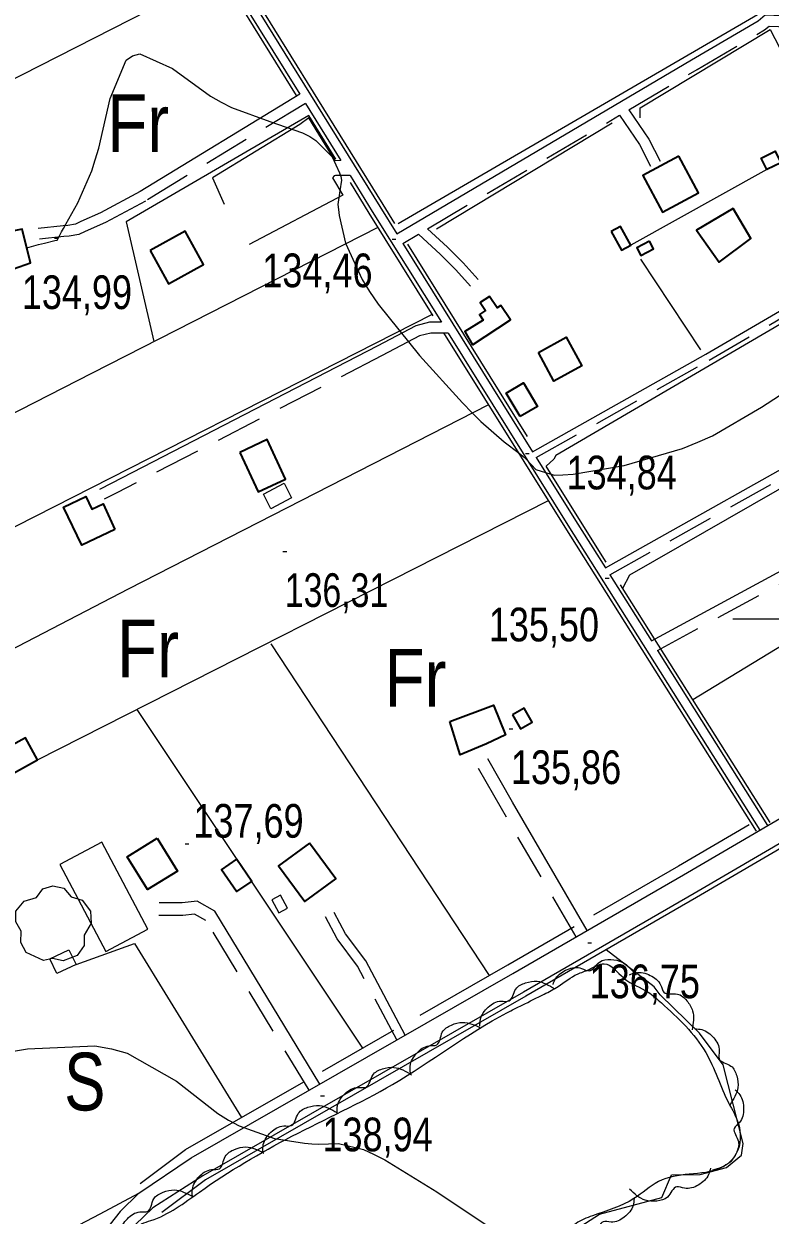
# Model space of a CAD drawing. Extents: x 487425 to 492029, y 4383576 to 4386788.
# Drawn here: x 490290.9 to 490484.7, y 4384845.1 to 4385154.5 of the extents above; entities that cross this region are included whole.
import ezdxf
from ezdxf.enums import TextEntityAlignment as Align

# ---------------------------------------------------------------- set-up
doc = ezdxf.new("R2010")
doc.units = 0
doc.header["$LTSCALE"] = 4
doc.linetypes.add('LONG_DASHED', pattern=[7.5, 6, -1.5])
doc.linetypes.add('MEDIUM_DASHED', pattern=[4.5, 3, -1.5])
for name, color, linetype, lineweight in [('1', 7, 'Continuous', 13), ('21', 7, 'Continuous', 25), ('25', 7, 'LONG_DASHED', 25), ('27', 7, 'Continuous', 25), ('29', 7, 'Continuous', 13), ('36', 7, 'Continuous', 25), ('38', 7, 'Continuous', 25), ('47', 7, 'Continuous', 35), ('51', 7, 'Continuous', 13), ('58', 7, 'Continuous', 25), ('7', 7, 'Continuous', 13), ('9', 7, 'Continuous', 13)]:
    doc.layers.add(name, color=color, linetype=linetype, lineweight=lineweight)
doc.layers.add('31', color=7, linetype='Continuous')

msp = doc.modelspace()

# ---------------------------------------------------------------- linework, layer by layer
at = {"layer": '1'}
msp.add_line((490475, 4385000), (490525, 4385000), dxfattribs=at)
at = {"layer": '21'}
for points in [[(490353.07, 4385032.38), (490358.44, 4385035.18), (490360.42, 4385031.38), (490355.05, 4385028.58)], [(490355.23, 4384927.03), (490357.08, 4384923.61), (490359.35, 4384924.84), (490357.5, 4384928.26)], [(490297.6, 4384911.68), (490302.57, 4384914.07), (490304.42, 4384910.24), (490299.45, 4384907.85)]]:
    msp.add_lwpolyline(points, close=True, dxfattribs=at)
at = {"layer": '25'}
msp.add_lwpolyline([(490433.1, 4384840.72), (490440.38, 4384845.42), (490456.52, 4384849.72), (490459.08, 4384855.56), (490466.51, 4384855.68), (490473.34, 4384857.54), (490477.24, 4384860.68), (490477.7, 4384863.75), (490472.44, 4384884.16), (490466.32, 4384892.43), (490456.15, 4384902.35), (490454.58, 4384904.46), (490442.06, 4384914.01)], dxfattribs=at)
at = {"layer": '27'}
for points in [[(490617.37, 4384698.42), (490601.81, 4384693.62), (490591.76, 4384693.65), (490581.71, 4384693.68), (490576.91, 4384694.3), (490571.22, 4384695.74), (490565.38, 4384696.95), (490561.4, 4384697.79), (490559.68, 4384698.32), (490552.49, 4384698.94), (490550.31, 4384698.35), (490522.61, 4384686.74), (490495.9, 4384680.59), (490488.46, 4384676.27), (490488.9, 4384674.24), (490493.38, 4384666.5), (490491.11, 4384661.41), (490488.03, 4384658.87), (490483.15, 4384656.04), (490478.87, 4384655.6), (490473.86, 4384657.12), (490454.42, 4384678.39), (490426.55, 4384709.07), (490413.85, 4384725.6), (490390.23, 4384749.37), (490372.38, 4384771.02), (490352.04, 4384791.1), (490332.69, 4384812.23), (490324.39, 4384821.02), (490321.78, 4384824.26), (490318.42, 4384829.14), (490316.41, 4384834.54), (490317.92, 4384838.06), (490319.65, 4384841.28), (490321.46, 4384842.85), (490323.86, 4384843.74), (490336.48, 4384851.13), (490360.44, 4384865.6), (490386.65, 4384879.1), (490416.32, 4384897.68), (490420.3, 4384899.69), (490426.01, 4384902.52), (490429.62, 4384904.53), (490434.65, 4384907.74), (490437.65, 4384908.93), (490441.55, 4384910.42), (490446.72, 4384906.66), (490453, 4384903.04), (490456.45, 4384900.25), (490467.95, 4384887.4), (490473.91, 4384874.26), (490476.44, 4384868.85), (490475.9, 4384861.13), (490472.06, 4384857.47), (490463.66, 4384855.77), (490455.7, 4384853.84), (490449.32, 4384849.44), (490438.51, 4384844.97), (490434.3, 4384842.96), (490429.94, 4384837.43), (490427.66, 4384828.43), (490427.25, 4384816.89), (490427.97, 4384807.51), (490429.3, 4384801.21), (490433.76, 4384787.33), (490439.88, 4384776.81), (490445.4, 4384769.75), (490455.04, 4384758.25), (490456.23, 4384753.97), (490456.81, 4384748.79), (490460.93, 4384747.06), (490467.91, 4384747.86), (490498.23, 4384759.32), (490526.16, 4384771.3), (490535.17, 4384775.92), (490539.68, 4384778.53), (490555.38, 4384788.38), (490560.34, 4384793.09), (490556.85, 4384802.33), (490547.98, 4384822.07), (490542.69, 4384831.84), (490537.93, 4384843.62), (490531.01, 4384861.41), (490527.97, 4384873.04), (490519.06, 4384879.07), (490516.75, 4384882.98), (490514.9, 4384889.28), (490519.37, 4384907.19), (490528.34, 4384921.18), (490538.42, 4384933.3), (490552.62, 4384941.58)], [(490428.3, 4384905), (490429.02, 4384906.63), (490432.03, 4384908.93), (490435.72, 4384909.22), (490437.67, 4384908.57), (490440.38, 4384910.87), (490443.3, 4384911.51), (490446.25, 4384910.85), (490449.86, 4384907.46)], [(490448.12, 4384907.53), (490449.8, 4384908.09), (490453.53, 4384907.41), (490456.24, 4384904.9), (490457.07, 4384903.02), (490460.59, 4384902.55), (490463.03, 4384900.83), (490464.54, 4384898.21), (490464.45, 4384893.25)], [(490409.32, 4384894.19), (490409.44, 4384895.96), (490411.49, 4384899.16), (490414.84, 4384900.71), (490416.89, 4384900.77), (490418.65, 4384903.85), (490421.17, 4384905.45), (490424.17, 4384905.86), (490428.73, 4384903.9)], [(490391.28, 4384882.06), (490391.21, 4384883.83), (490392.91, 4384887.22), (490396.08, 4384889.11), (490398.12, 4384889.38), (490399.55, 4384892.63), (490401.89, 4384894.49), (490404.83, 4384895.2), (490409.57, 4384893.73)], [(490465.15, 4384893.5), (490466.91, 4384893.32), (490470.04, 4384891.17), (490471.48, 4384887.77), (490471.46, 4384885.72), (490474.49, 4384883.85), (490476, 4384881.28), (490476.3, 4384878.27), (490474.19, 4384873.78)], [(490372.2, 4384871.76), (490372.31, 4384873.53), (490374.33, 4384876.74), (490377.67, 4384878.31), (490379.73, 4384878.38), (490381.47, 4384881.47), (490383.99, 4384883.09), (490386.98, 4384883.51), (490391.55, 4384881.58)], [(490475.59, 4384877.66), (490476.82, 4384876.38), (490477.8, 4384872.72), (490476.69, 4384869.2), (490475.35, 4384867.64), (490476.43, 4384864.26), (490475.91, 4384861.33), (490474.19, 4384858.84), (490469.67, 4384856.79)], [(490352.97, 4384861.7), (490353.06, 4384863.47), (490355.05, 4384866.7), (490358.37, 4384868.31), (490360.42, 4384868.4), (490362.14, 4384871.52), (490364.63, 4384873.16), (490367.62, 4384873.61), (490372.21, 4384871.74)], [(490334.65, 4384850.02), (490334.63, 4384851.8), (490336.41, 4384855.15), (490339.63, 4384856.96), (490341.67, 4384857.18), (490343.18, 4384860.4), (490345.56, 4384862.2), (490348.52, 4384862.84), (490353.22, 4384861.26)], [(490469.17, 4384857.36), (490468.69, 4384855.66), (490466.02, 4384852.95), (490462.43, 4384852.13), (490460.41, 4384852.5), (490458.04, 4384849.84), (490455.24, 4384848.8), (490452.23, 4384849.02), (490448.17, 4384851.88)], [(490315.89, 4384839.12), (490315.9, 4384840.89), (490317.75, 4384844.21), (490321, 4384845.96), (490323.04, 4384846.14), (490324.61, 4384849.33), (490327.03, 4384851.08), (490330, 4384851.67), (490334.67, 4384850)], [(490449.34, 4384849.42), (490449.09, 4384847.66), (490446.81, 4384844.63), (490443.36, 4384843.33), (490441.31, 4384843.43), (490439.32, 4384840.48), (490436.68, 4384839.07), (490433.67, 4384838.89), (490429.27, 4384841.18)]]:
    msp.add_spline(points, degree=3, dxfattribs=at)
at = {"layer": '29'}
msp.add_lwpolyline([(490296, 4384911.26), (490291.46, 4384913.38), (490290.05, 4384915.92), (490290.15, 4384918.9), (490288.78, 4384921.31), (490288.82, 4384924.06), (490290.98, 4384926.66), (490294.17, 4384927.66), (490295.82, 4384929.85), (490298.39, 4384930.68), (490301.25, 4384930.03), (490303.2, 4384927.76), (490306.01, 4384926.94), (490308.14, 4384924.09), (490308.38, 4384920.96), (490306.5, 4384917.81), (490306.5, 4384915.13), (490304.68, 4384912.52), (490301.06, 4384911.18), (490298.29, 4384911.81)], close=True, dxfattribs=at)
at = {"layer": '36'}
for points in [[(490810.5, 4385130.98), (490748.83, 4385094.26), (490648.55, 4385035.69), (490532.81, 4384968.32), (490464.98, 4384928.7), (490420.66, 4384903.02), (490337.39, 4384855.31), (490324.37, 4384847.05)], [(490320.75, 4384850.81), (490334.31, 4384860.01), (490417.86, 4384907.88), (490462.16, 4384933.55), (490529.98, 4384973.17), (490560.7, 4384991.06)], [(490320.75, 4384850.81), (490315.86, 4384846.11), (490311.96, 4384841.17), (490311.11, 4384835.98), (490311.09, 4384829.32), (490311.85, 4384823.86), (490315.09, 4384817.04), (490319.53, 4384811.61), (490326.04, 4384805.35)], [(490324.37, 4384847.05), (490319.74, 4384842.6), (490316.89, 4384838.99), (490316.33, 4384835.55), (490316.31, 4384829.67), (490316.91, 4384825.38), (490319.54, 4384819.86), (490323.4, 4384815.14), (490329.15, 4384808.37)]]:
    msp.add_lwpolyline(points, dxfattribs=at)
at = {"layer": '38'}
for p, q in [((490364, 4385133.82), (490373.16, 4385119.03)), ((490389.28, 4385097.5), (490423.01, 4385043.4)), ((490443.04, 4385011.42), (490453.83, 4384994.28)), ((490455.39, 4384991.8), (490484.02, 4384946.32))]:
    msp.add_line(p, q, dxfattribs=at)
at = {"layer": '38', "linetype": 'MEDIUM_DASHED'}
for p, q in [((490395.66, 4385101.27), (490445.59, 4385130.77)), ((490389.28, 4385097.5), (490393.32, 4385099.89))]:
    msp.add_line(p, q, dxfattribs=at)
at = {"layer": '38'}
for points in [[(490334.51, 4385181.34), (490337.39, 4385176.79), (490362.51, 4385136.22)], [(490340.67, 4385175.93), (490383.33, 4385107.05), (490387.76, 4385099.95)], [(490387.76, 4385099.95), (490464.25, 4385145.14), (490481.58, 4385155.3), (490483.41, 4385156.85), (490490.1, 4385156.57), (490494.37, 4385154.07), (490499.23, 4385147.96), (490502.03, 4385144.77), (490506.71, 4385141.08)], [(490362.51, 4385136.22), (490321.04, 4385110.93), (490310.82, 4385105.42), (490305.63, 4385103.14), (490304.31, 4385102.52), (490302.31, 4385102.15), (490301.04, 4385102.09), (490294.58, 4385101.35)], [(490448, 4385132.19), (490453.14, 4385124.6), (490456.12, 4385118.82)], [(490373.16, 4385119.03), (490371.72, 4385118.89), (490364.84, 4385130.09), (490362.51, 4385128.33), (490339.9, 4385114.52), (490342.88, 4385107.69)], [(490423.01, 4385043.4), (490467.97, 4385068.7), (490523.71, 4385101.29), (490556.46, 4385119.73)], [(490375.6, 4385115.09), (490371.84, 4385115.1), (490371.47, 4385115.03), (490371.02, 4385114.5), (490373.7, 4385110), (490349.37, 4385097.17)], [(490375.6, 4385115.09), (490381.34, 4385105.81), (490399.31, 4385077)], [(490395.66, 4385101.27), (490400.85, 4385096.47), (490404.96, 4385092.41), (490408.82, 4385088.08)], [(490441.89, 4385013.23), (490505.76, 4385049.08), (490525.62, 4385060.64), (490527.93, 4385063.61), (490529.59, 4385066.47), (490530.72, 4385068.66), (490531.14, 4385072.23), (490530.65, 4385082.91)], [(490399.31, 4385077), (490396.24, 4385077.01), (490392.63, 4385076.12), (490382.66, 4385070.83), (490313.73, 4385035.2), (490310.5, 4385033.57)], [(490401.06, 4385074.19), (490432.16, 4385024.3), (490481.99, 4384945.13)], [(490423.95, 4385041.9), (490434.15, 4385025.54), (490441.89, 4385013.23)], [(490453.83, 4384994.28), (490524.42, 4385032.45), (490539.46, 4385039.91)], [(490437.16, 4384919.07), (490417.75, 4384952.36), (490411.33, 4384963.63)], [(490367.76, 4384879.17), (490340.51, 4384924.09), (490335.88, 4384926.68), (490331.98, 4384926.2), (490325.98, 4384926.22)], [(490389.94, 4384891.89), (490379.65, 4384911.17), (490374.42, 4384918.23), (490371.42, 4384923.77)], [(490296.44, 4384837.58), (490301.58, 4384840.74), (490310.67, 4384845.51), (490320.75, 4384850.81)]]:
    msp.add_lwpolyline(points, dxfattribs=at)
at = {"layer": '38', "linetype": 'MEDIUM_DASHED'}
for points in [[(490448, 4385132.19), (490465.72, 4385142.66), (490483.25, 4385152.94), (490484.42, 4385153.92), (490489.26, 4385153.72), (490492.45, 4385151.85), (490497.01, 4385146.11), (490500.04, 4385142.67), (490504.93, 4385138.82)], [(490364, 4385133.82), (490322.44, 4385108.48), (490312.06, 4385102.88), (490306.79, 4385100.57), (490305.17, 4385099.81), (490302.63, 4385099.35), (490301.27, 4385099.28), (490294.9, 4385098.55)], [(490445.59, 4385130.77), (490450.73, 4385123.17), (490453.64, 4385117.53)], [(490423.95, 4385041.9), (490468.85, 4385067.17), (490524.59, 4385099.76), (490557.32, 4385118.19)], [(490393.32, 4385099.89), (490399.06, 4385094.59), (490403.08, 4385090.62), (490406.88, 4385086.35)], [(490443.04, 4385011.42), (490506.83, 4385047.22), (490527.06, 4385058.99), (490529.72, 4385062.41), (490531.47, 4385065.44), (490532.81, 4385068.02), (490533.29, 4385072.16), (490532.8, 4385083.01)], [(490401.06, 4385074.19), (490396.57, 4385074.21), (490393.64, 4385073.48), (490383.96, 4385068.35), (490315.01, 4385032.71), (490311.77, 4385031.07)], [(490455.39, 4384991.8), (490525.77, 4385029.86), (490540.76, 4385037.29)], [(490434.31, 4384917.41), (490414.89, 4384950.71), (490408.46, 4384961.99)], [(490364.93, 4384877.55), (490338.17, 4384921.66), (490335.22, 4384923.31), (490332.18, 4384922.94), (490325.97, 4384922.96)], [(490387.74, 4384890.62), (490377.5, 4384909.81), (490372.27, 4384916.86), (490369.18, 4384922.56)]]:
    msp.add_lwpolyline(points, dxfattribs=at)
at = {"layer": '47'}
for points in [[(490487.47, 4385118.43), (490483.84, 4385116.66), (490482.38, 4385119.64), (490486.01, 4385121.41)], [(490460.93, 4385120.16), (490451.62, 4385115.12), (490456.77, 4385105.62), (490466.08, 4385110.66)], [(490475.06, 4385106.54), (490465.6, 4385100.95), (490471.42, 4385092.61), (490479.69, 4385098.73)], [(490284.01, 4385105.17), (490268.7, 4385098.77), (490271.31, 4385094.86), (490277.91, 4385097.02), (490279.7, 4385093.26), (490287.13, 4385094.29), (490288.17, 4385090.91), (490292.59, 4385092.47), (490290.45, 4385101.18), (490285.8, 4385100.22)], [(490323.65, 4385095.68), (490328.43, 4385087.02), (490337.51, 4385092.04), (490332.73, 4385100.7)], [(490443.4, 4385100.56), (490446.05, 4385095.69), (490448.49, 4385097.02), (490445.84, 4385101.89)], [(490453.37, 4385098.06), (490450.06, 4385096.34), (490451.11, 4385094.32), (490454.42, 4385096.04)], [(490407.4, 4385071.13), (490417.24, 4385077.62), (490414.75, 4385081.39), (490413.75, 4385080.74), (490411.79, 4385083.74), (490409.36, 4385082.17), (490410.74, 4385080.02), (490409.18, 4385079.03), (490410.12, 4385077.53), (490405.38, 4385074.57)], [(490424.49, 4385069.13), (490431.75, 4385073.11), (490435.8, 4385065.72), (490428.54, 4385061.74)], [(490419.79, 4385052.5), (490416.17, 4385058.63), (490420.64, 4385061.27), (490424.26, 4385055.14)], [(490346.96, 4385043.2), (490351.72, 4385032.94), (490358.86, 4385036.26), (490354.1, 4385046.52)], [(490314.5, 4385023.2), (490305.94, 4385019.1), (490301.19, 4385029.01), (490306.98, 4385031.79), (490308.55, 4385028.5), (490311.44, 4385029.88)], [(490401.48, 4384973.3), (490412.82, 4384977.54), (490415.94, 4384969.88), (490410.99, 4384967.57), (490404.15, 4384964.67)], [(490417.76, 4384975.05), (490419.85, 4384971.43), (490422.85, 4384973.16), (490420.76, 4384976.78)], [(490281.24, 4384956.12), (490294.45, 4384963.35), (490291.31, 4384969.06), (490285.15, 4384965.67), (490283.09, 4384969.39), (490275.95, 4384965.44)], [(490325.51, 4384943.01), (490330.78, 4384934.5), (490322.99, 4384929.67), (490317.72, 4384938.18)], [(490365.09, 4384941.77), (490357.02, 4384935.83), (490363.85, 4384926.55), (490371.92, 4384932.49)], [(490346.19, 4384937.55), (490350.06, 4384931.85), (490346.09, 4384929.15), (490342.22, 4384934.85)]]:
    msp.add_lwpolyline(points, close=True, dxfattribs=at)
at = {"layer": '51'}
for p, q in [((490371.93, 4385119.34), (490364.87, 4385130.74)), ((490398.04, 4385101.23), (490443.64, 4385128.76)), ((490483.84, 4385116.66), (490448.49, 4385097.02)), ((490421.67, 4385047.38), (490390.56, 4385097.29)), ((490451.03, 4385093.42), (490466.63, 4385069.83)), ((490164.16, 4384960.64), (490396.97, 4385079.11)), ((490294.45, 4384963.35), (490427.1, 4385030.75)), ((490484.66, 4384947.1), (490445.84, 4385008.79)), ((490411.79, 4384907.38), (490355.13, 4384993.53)), ((490378.89, 4384888.53), (490320.3, 4384976.48)), ((490368.39, 4384882.52), (490386.96, 4384893.16))]:
    msp.add_line(p, q, dxfattribs=at)
for points in [[(490640.08, 4385250.83), (490557.3, 4385201.07), (490388.07, 4385102.53)], [(490770.88, 4385242.15), (490597.31, 4385141.11), (490508.68, 4385088.97), (490429.06, 4385042.42), (490428.53, 4385041.45), (490426.53, 4385039.6)], [(490446.39, 4385007.93), (490448.23, 4385011.4), (490537.91, 4385062.86), (490618.28, 4385109.18), (490787.53, 4385210)], [(490361.68, 4385135.9), (490336.64, 4385176.32), (490334.35, 4385179.96)], [(490387.24, 4385102.62), (490384.15, 4385107.56), (490342.18, 4385175.36)], [(490084.66, 4385035.56), (490205.94, 4385098.37), (490342.02, 4385167.65)], [(490450.92, 4385130.08), (490450.92, 4385132.71), (490484.73, 4385153), (490499.41, 4385124.61), (490558.07, 4385159.26)], [(490364.87, 4385130.74), (490317.45, 4385103.12), (490324.62, 4385071.99)], [(490811.13, 4385129.93), (490749.45, 4385093.21), (490649.17, 4385034.64), (490533.43, 4384967.27), (490465.59, 4384927.64), (490421.27, 4384901.96), (490338.06, 4384854.29), (490326.72, 4384845.79)], [(490397.21, 4385078.71), (490380.59, 4385105.35), (490375.69, 4385113.27)], [(490143.79, 4384979.56), (490308.7, 4385063.86), (490382.85, 4385101.74)], [(490636.7, 4385078.02), (490503.99, 4385002.91), (490464.62, 4384978.96)], [(490481.12, 4384944.87), (490431.41, 4385023.83), (490399.97, 4385074.27)], [(490185.66, 4384939.08), (490318.06, 4385007.74), (490411.59, 4385055.65)], [(490442.1, 4385014.74), (490434.97, 4385026.05), (490426.53, 4385039.6)], [(490479.21, 4384946.51), (490460.86, 4384935.79), (490438.82, 4384923.02)], [(490393.82, 4384897.09), (490416.57, 4384910.12), (490433.75, 4384920.08)], [(490304.42, 4384910.24), (490319.58, 4384915.66), (490347.39, 4384870.49)], [(490321.07, 4384853.32), (490332.89, 4384862.18), (490363.57, 4384879.76)]]:
    msp.add_lwpolyline(points, dxfattribs=at)
at = {"layer": '58'}
msp.add_lwpolyline([(490323.04, 4384919.4), (490311.11, 4384941.95), (490300.22, 4384936.19), (490312.15, 4384913.64)], close=True, dxfattribs=at)
at = {"layer": '7'}
for p, q in [((490298.86, 4385098.82), (490299.86, 4385098.82)), ((490386.51, 4385098.63), (490387.51, 4385098.63)), ((490421.14, 4385042.89), (490422.14, 4385042.89)), ((490358.15, 4385017.44), (490359.15, 4385017.44)), ((490441.88, 4385010.52), (490442.88, 4385010.52)), ((490416.87, 4384971.45), (490417.87, 4384971.45)), ((490332.73, 4384941.56), (490333.73, 4384941.56)), ((490437.32, 4384915.83), (490438.32, 4384915.83)), ((490367.92, 4384876.08), (490368.92, 4384876.08))]:
    msp.add_line(p, q, dxfattribs=at)
at = {"layer": '9'}
for points in [[(490291.63, 4385096.36), (490292.85, 4385096.68), (490294.72, 4385097.16), (490296.25, 4385097.56), (490298.96, 4385098.2), (490299.39, 4385098.31), (490299.49, 4385098.37), (490299.58, 4385098.44), (490299.81, 4385098.78), (490300.69, 4385100.45), (490301.18, 4385101.36), (490301.79, 4385102.46), (490304.88, 4385108.05), (490308.49, 4385116.37), (490309.41, 4385119.19), (490310.31, 4385122.24), (490313.29, 4385135.12), (490317.46, 4385145.04), (490319.11, 4385146.23), (490320.97, 4385146.73), (490329.47, 4385142.89), (490339.36, 4385135.75), (490342.09, 4385134.17), (490344.83, 4385132.76), (490354.73, 4385129.11), (490363.24, 4385126.17), (490365.1, 4385125.21), (490366.74, 4385124.19), (490370.9, 4385119.98), (490372.88, 4385115.81), (490373.16, 4385114.82), (490373.33, 4385113.89), (490372.93, 4385111.12), (490372.44, 4385107.63), (490372.55, 4385106.26), (490372.76, 4385104.7), (490374.37, 4385097.59), (490378.72, 4385088.08), (490380.65, 4385085.01), (490382.9, 4385081.75), (490393.64, 4385068.39), (490404.79, 4385056.08), (490407.29, 4385053.47), (490409.54, 4385051.21), (490415.57, 4385045.96), (490419.49, 4385043.04), (490420.42, 4385042.26), (490421.28, 4385041.49), (490423.79, 4385038.78), (490428.57, 4385037.34), (490430.86, 4385037.36), (490433.56, 4385037.57), (490446.79, 4385039.84), (490461.96, 4385044.26), (490465.88, 4385045.83), (490469.68, 4385047.54), (490482.41, 4385054.94), (490493.25, 4385061.93)], [(490276.22, 4384885.71), (490291.86, 4384888.29), (490309.33, 4384889.06), (490313.63, 4384888.35), (490317.7, 4384887.24), (490330.49, 4384879.89), (490341.26, 4384871.55), (490344.06, 4384869.81), (490346.78, 4384868.33), (490355.96, 4384865.05), (490363.79, 4384863.85), (490365.65, 4384863.67), (490367.39, 4384863.56), (490372.57, 4384863.74), (490379.12, 4384862.19), (490381.71, 4384860.99), (490384.65, 4384859.47), (490398.08, 4384851.18), (490410.65, 4384842.78)]]:
    msp.add_lwpolyline(points, dxfattribs=at)

# ---------------------------------------------------------------- texts
at = {"layer": '31'}
for s, width, p in [('Fr', 0.85, (490320.58, 4385121.23)), ('Fr', 0.85, (490323.11, 4384984.77)), ('Fr', 0.85, (490392.57, 4384977.19)), ('S', 0.8, (490306.7, 4384872.32))]:
    msp.add_text(s, height=15, dxfattribs=dict(at, width=width)).set_placement(p, align=Align.CENTER)
at = {"layer": '7'}
for s, width, p in [('134,46', 0.8, (490352.8, 4385086.11)), ('134,99', 0.8, (490290.34, 4385080.44)), ('134,84', 0.8, (490431.81, 4385033.61)), ('136,31', 0.75, (490358.65, 4385003.07)), ('135,50', 0.8, (490411.61, 4384994.14)), ('135,86', 0.8, (490417.37, 4384957.08)), ('137,69', 0.8, (490334.9, 4384943.15)), ('136,75', 0.8, (490437.82, 4384901.46)), ('138,94', 0.8, (490368.42, 4384861.71))]:
    msp.add_text(s, height=8.75, dxfattribs=dict(at, width=width)).set_placement(p)

doc.saveas('drawing.dxf')
